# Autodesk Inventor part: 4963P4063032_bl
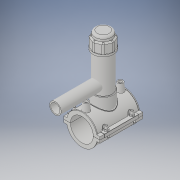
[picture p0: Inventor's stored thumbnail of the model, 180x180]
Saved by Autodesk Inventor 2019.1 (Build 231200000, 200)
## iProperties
Created: 2017-07
Part Number: 4963P4063032_bl
Material: Generic
Document SubType Name: Modeling
Designer: KIM
Density: 1 g/cm^3
Appearance: Default
Author: KIM
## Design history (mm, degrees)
derived "4963P4.ipt"
feature "Solid1::4963P4.ipt" dims "ScaleForDerivedMember" = 10
feature "Solid2::4963P4.ipt" dims "ScaleForDerivedMember" = 10
feature "Solid3::4963P4.ipt" dims "ScaleForDerivedMember" = 10
tag "TaggingFeature1"
body "Solid1"
body "Solid2"
body "Solid3"
other parameters: "d0" = 63 [user parameter], "d3" = 15.75 [user parameter], "d4" = 118 [user parameter], "d5" = 0 [user parameter], "d6" = 0.1 [user parameter], "d8" = 0 [user parameter], "d19" = 6 [user parameter], "d20" = 6 [user parameter], "d21" = 70.8 [user parameter], "d23" = 0 [user parameter], "d24" = 35.4 [user parameter], "d26" = 0 [user parameter], "d27" = 3 [user parameter], "d28" = 3 [user parameter], "d29" = 3 [user parameter], "d30" = 21 [user parameter], "d31" = 6 [user parameter], "d32" = 0 [user parameter], "d33" = 0 [user parameter], "d34" = 0.6 [user parameter], "d40" = 42.588 [user parameter], "d41" = 56.7 [user parameter], "d43" = 0 [user parameter], "d45" = 0 [user parameter], "d47" = 111.75 [user parameter], "d70" = 15 [user parameter], "d72" = 0 [user parameter], "d73" = 6 [user parameter], "d75" = 5 [user parameter], "d76" = 0 [user parameter], "d77" = 3.15 [user parameter], "d78" = 61.5 [user parameter], "d79" = 15 [user parameter], "d80" = 47.2 [user parameter], "d82" = 5 deg [user parameter], "d84" = 4 [user parameter], "d85" = 14 [user parameter], "d86" = 0 [user parameter], "d87" = 3 [user parameter], "d88" = 0 [user parameter], "d89" = 1 [user parameter], "d90" = 1 [user parameter], "d91" = 94.4 [user parameter], "d92" = 0 [user parameter], "d93" = 0.5 [user parameter], "d94" = 33.15789 [user parameter], "d96" = 83.538 [user parameter], "d97" = 2.36 [user parameter], "d98" = 0 [user parameter], "d102" = 0.63 [user parameter], "d120" = 140 deg [user parameter], "d121" = 24.228 [user parameter], "d122" = 20 deg [user parameter], "d123" = 163.8 [user parameter], "d124" = 49.14 [user parameter], "d126" = 0 [user parameter], "d143" = 64.89 [user parameter], "d145" = 14.53846 [user parameter], "d149" = 0.945 [user parameter], "d150" = 15.99231 [user parameter], "d153" = 118 [user parameter], "d154" = 0 [user parameter], "d156" = 40.95 [user parameter], "d157" = 160 deg [user parameter], "d159" = 3.78 [user parameter], "d161" = 0.945 [user parameter], "d162" = 70.8 [user parameter], "d163" = 0 [user parameter], "d164" = 31.5 [user parameter], "d167" = 6.3 [user parameter], "d168" = 39.95122 [user parameter], "d170" = 3.75 [user parameter], "d172" = 0 [user parameter], "d173" = 1 [user parameter], "d175" = 31.5 [user parameter], "d176" = 20 deg [user parameter], "d177" = 4.41 [user parameter], "d178" = 18.9 [user parameter], "d180" = 0 [user parameter], "d183" = 7.56 [user parameter], "d184" = 3.528 [user parameter], "d185" = 38.35 [user parameter], "d186" = 38.35 [user parameter], "d187" = 40.95 [user parameter], "d188" = 5.67 [user parameter], "d189" = 4.41 [user parameter], "d190" = 0 [user parameter], "d191" = 61.425 [user parameter], "d193" = 8 [user parameter], "d194" = 4.13 [user parameter], "d195" = 90 deg [user parameter], "d197" = 0 [user parameter], "d199" = 0 [user parameter], "d200" = 9.45 [user parameter], "d202" = 0 [user parameter], "d203" = 177 [user parameter], "d204" = 53.865 [user parameter], "d205" = 39.69 [user parameter], "d206" = 48.195 [user parameter], "d207" = 132.75 [user parameter], "d208" = 138.06 [user parameter], "d209" = 164.61 [user parameter], "d210" = 48.762 [user parameter], "d211" = 56.7 [user parameter], "d212" = 45.36 [user parameter], "d213" = 36 [user parameter], "d216" = 0 [user parameter], "d217" = 6.3 [user parameter], "d218" = 6.3 [user parameter], "d219" = 1.26 [user parameter], "d222" = 63 [user parameter], "d224" = 0 [user parameter], "d225" = 56 [user parameter], "d226" = 32 [user parameter], "d227" = 25.6 [user parameter], "d228" = 132 [user parameter], "d230" = 3.78 [user parameter], "d_" = 63 [user parameter], "L_" = 118 [user parameter], "d_t" = 6 [user parameter]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
